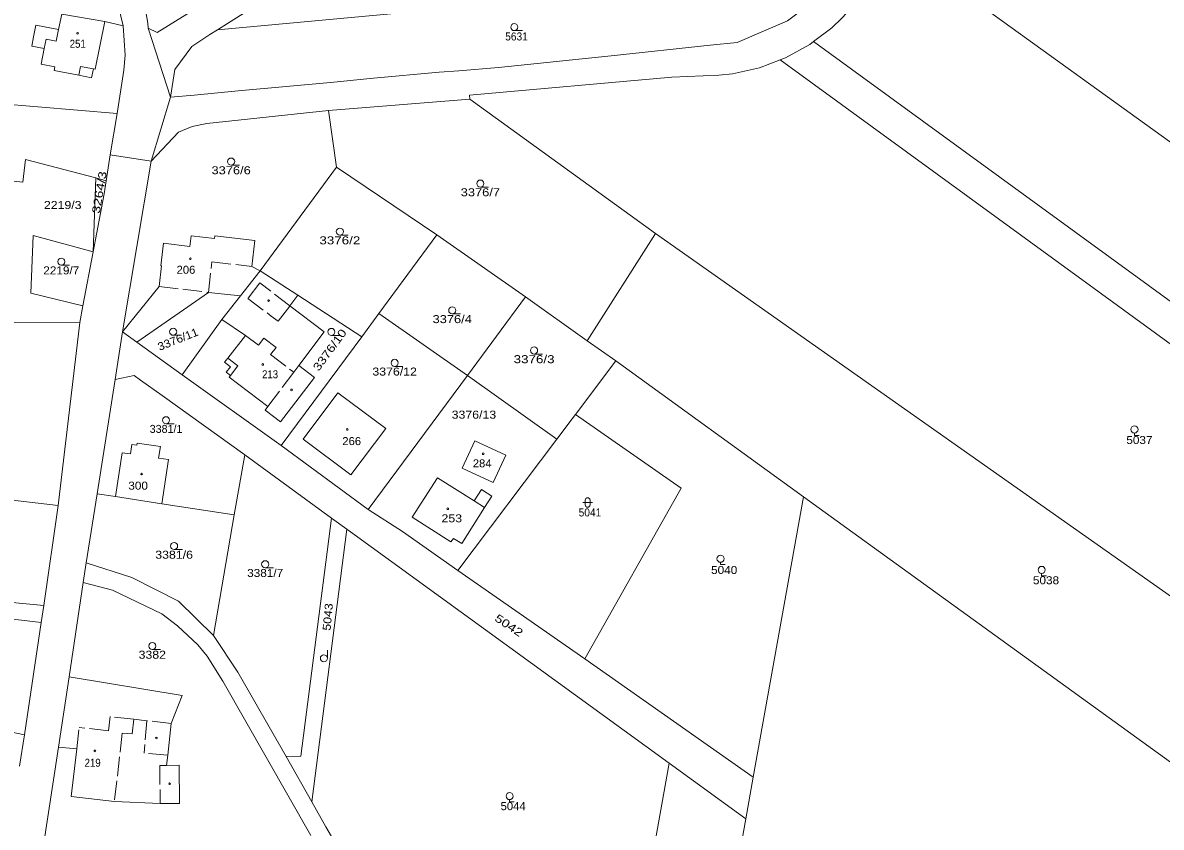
# Model space of a CAD drawing. Extents: x -590528 to -586543, y -1119609 to -1116685.
# Drawn here: x -588604.8 to -588363.1, y -1118023.6 to -1117852.7 of the extents above; entities that cross this region are included whole.
import ezdxf
from ezdxf.enums import TextEntityAlignment as Align

# ---------------------------------------------------------------- set-up
doc = ezdxf.new("R2010")
doc.units = 0
doc.header["$LTSCALE"] = 0.68
doc.linetypes.add('LONG_DASHED', pattern=[7.5, 6, -1.5])
for name, color, linetype, lineweight in [('1', 7, 'Continuous', 13), ('2', 7, 'LONG_DASHED', 13), ('3', 7, 'Continuous', 13), ('6', 7, 'Continuous', 13)]:
    doc.layers.add(name, color=color, linetype=linetype, lineweight=lineweight)

msp = doc.modelspace()

# ---------------------------------------------------------------- linework, layer by layer
at = {"layer": '1'}
for p, q in [((-588417.18, -1117837.61), (-588270.98, -1117943.18)), ((-588585.36, -1117845.73), (-588583.47, -1117853.36)), ((-588587.41, -1117852.47), (-588583.47, -1117853.36)), ((-588436.89, -1117856.73), (-588289.86, -1117963.81)), ((-588443.99, -1117860.6), (-588299, -1117966.2)), ((-588589.8, -1117862.5), (-588589.41, -1117862.58)), ((-588617.56, -1117869.2), (-588584.77, -1117872)), ((-588573.44, -1117868.51), (-588577.57, -1117882.1)), ((-588584.77, -1117872), (-588586.22, -1117880.79)), ((-588538.19, -1117883.42), (-588539.87, -1117871.36)), ((-588568.82, -1117874.77), (-588565.75, -1117874.14)), ((-588577.57, -1117882.1), (-588571.73, -1117875.95)), ((-588571.73, -1117875.95), (-588568.82, -1117874.77)), ((-588586.22, -1117880.79), (-588587.08, -1117886.28)), ((-588586.22, -1117880.79), (-588577.57, -1117882.1)), ((-588577.57, -1117882.1), (-588583.66, -1117918.35)), ((-588589.88, -1117901.39), (-588589.29, -1117885.69)), ((-588587.08, -1117886.28), (-588587.54, -1117889.06)), ((-588602.58, -1117897.93), (-588603.08, -1117910.13)), ((-588589.88, -1117901.39), (-588602.58, -1117897.93)), ((-588569.06, -1117897.94), (-588569.34, -1117900.22)), ((-588564.1, -1117898.55), (-588569.06, -1117897.94)), ((-588564.02, -1117897.96), (-588564.1, -1117898.55)), ((-588555.53, -1117899), (-588564.02, -1117897.96)), ((-588516.85, -1117897.74), (-588498.06, -1117910.93)), ((-588470.44, -1117897.46), (-588324.73, -1118000.18)), ((-588574.9, -1117899.54), (-588575.49, -1117904.32)), ((-588569.34, -1117900.22), (-588574.9, -1117899.54)), ((-588556.2, -1117904.51), (-588555.53, -1117899)), ((-588575.34, -1117904.34), (-588575.87, -1117908.71)), ((-588575.49, -1117904.32), (-588575.34, -1117904.34)), ((-588556.2, -1117904.51), (-588554.41, -1117905.4)), ((-588592.06, -1117912.86), (-588603.08, -1117910.13)), ((-588575.87, -1117908.71), (-588583.66, -1117918.35)), ((-588565.39, -1117909.98), (-588580.55, -1117920.58)), ((-588565.39, -1117909.98), (-588558.59, -1117910.71)), ((-588548.08, -1117912.83), (-588546.37, -1117910.61)), ((-588540.82, -1117918.39), (-588548.08, -1117912.83)), ((-588484.94, -1117920.26), (-588498.06, -1117910.93)), ((-588592.7, -1117916.38), (-588597.27, -1117955.25)), ((-588570.94, -1117927.5), (-588562.55, -1117915.74)), ((-588562.55, -1117915.74), (-588557.52, -1117919.11)), ((-588583.66, -1117918.35), (-588580.55, -1117920.58)), ((-588532.81, -1117919.4), (-588549.96, -1117942.53)), ((-588546.22, -1117925.54), (-588540.82, -1117918.39)), ((-588580.55, -1117920.58), (-588570.94, -1117927.5)), ((-588439.06, -1117953.37), (-588478.89, -1117924.55)), ((-588546.22, -1117925.54), (-588542.88, -1117928.08)), ((-588585.22, -1117928.51), (-588589.01, -1117952.76)), ((-588575.18, -1117931.9), (-588579.81, -1117928.6)), ((-588552.75, -1117934.24), (-588561.01, -1117928.02)), ((-588575.18, -1117931.9), (-588557.68, -1117944.46)), ((-588552.75, -1117934.24), (-588553.34, -1117935.02)), ((-588464.99, -1117951.53), (-588487.42, -1117935.9)), ((-588557.68, -1117944.46), (-588559.9, -1117957.23)), ((-588539.23, -1117957.91), (-588557.68, -1117944.46)), ((-588516.76, -1117949.37), (-588522.13, -1117957.7)), ((-588597.27, -1117955.25), (-588624.74, -1117952.12)), ((-588589.01, -1117952.76), (-588591.33, -1117967.41)), ((-588439.06, -1117953.37), (-588306.86, -1118049.02)), ((-588597.27, -1117955.25), (-588600.36, -1117976.47)), ((-588575.25, -1117954.87), (-588559.9, -1117957.23)), ((-588531.43, -1117956.07), (-588524.16, -1117960.8)), ((-588559.9, -1117957.23), (-588564.34, -1117982.82)), ((-588545.75, -1118008.5), (-588539.23, -1117957.91)), ((-588535.99, -1117960.26), (-588539.23, -1117957.91)), ((-588524.16, -1117960.8), (-588512.39, -1117969.08)), ((-588571.71, -1117975.59), (-588581.67, -1117970.56)), ((-588628.23, -1117973.84), (-588600.36, -1117976.47)), ((-588564.34, -1117982.82), (-588571.71, -1117975.59)), ((-588600.89, -1117980.09), (-588600.36, -1117976.47)), ((-588608.69, -1117979.19), (-588600.89, -1117980.09)), ((-588600.89, -1117980.09), (-588604.44, -1118003.96)), ((-588559.12, -1117990.64), (-588564.34, -1117982.82)), ((-588562.31, -1117992.56), (-588543.64, -1118025.35)), ((-588548.85, -1118008.56), (-588559.12, -1117990.64)), ((-588573.26, -1118001.55), (-588570.99, -1117995.58)), ((-588574.03, -1118008.28), (-588573.26, -1118001.55)), ((-588604.44, -1118003.96), (-588605.52, -1118010.57)), ((-588600.51, -1118028.32), (-588597.22, -1118006.55)), ((-588594.52, -1118017.03), (-588593.36, -1118006.95)), ((-588574.28, -1118010.44), (-588574.03, -1118008.28)), ((-588548.85, -1118008.56), (-588545.75, -1118008.5)), ((-588543.46, -1118018.15), (-588548.85, -1118008.56)), ((-588571.6, -1118010.42), (-588574.28, -1118010.44)), ((-588571.54, -1118018.52), (-588571.6, -1118010.42)), ((-588451.28, -1118021.8), (-588467.56, -1118009.97)), ((-588585.33, -1118018.08), (-588594.52, -1118017.03)), ((-588575.64, -1118018.55), (-588585.33, -1118018.08)), ((-588575.64, -1118018.55), (-588571.54, -1118018.52))]:
    msp.add_line(p, q, dxfattribs=at)
for points in [[(-588436.89, -1117856.73), (-588432.98, -1117853.83), (-588430.89, -1117851.77), (-588424.08, -1117844.39), (-588417.18, -1117837.61), (-588385.65, -1117806.64)], [(-588514.05, -1117825.76), (-588545.49, -1117843.44), (-588552.09, -1117847.24), (-588558.61, -1117851.17), (-588563.45, -1117854.2), (-588515.09, -1117849.79)], [(-588579.44, -1117845.88), (-588578.22, -1117852.82), (-588578.15, -1117853.87), (-588576.25, -1117854.8), (-588570, -1117850.87), (-588560.11, -1117845.04), (-588543.67, -1117835.8), (-588534.47, -1117830.19)], [(-588431.73, -1117842.18), (-588438.44, -1117849.32), (-588442.39, -1117852.33), (-588453.1, -1117856.88), (-588458.84, -1117857.49), (-588479.87, -1117859.78), (-588503.81, -1117862.19), (-588512.2, -1117862.93), (-588516.4, -1117863.24)], [(-588596.48, -1117850.88), (-588597.22, -1117854.15), (-588602.02, -1117853.2), (-588602.52, -1117855.7), (-588602.91, -1117857.66), (-588600.26, -1117858.18), (-588600.92, -1117861.52), (-588597.98, -1117862.1), (-588598.12, -1117862.83)], [(-588596.48, -1117850.88), (-588587.41, -1117852.47), (-588589.41, -1117862.58)], [(-588583.47, -1117853.36), (-588583.09, -1117859.57), (-588583.33, -1117862.78), (-588584.77, -1117872)], [(-588578.15, -1117853.87), (-588573.44, -1117868.51), (-588572.49, -1117862.67), (-588568.92, -1117857.74), (-588565.07, -1117855.21), (-588563.45, -1117854.2)], [(-588436.89, -1117856.73), (-588437.7, -1117857.34), (-588442.86, -1117860.17), (-588443.99, -1117860.6)], [(-588443.99, -1117860.6), (-588448.36, -1117862.26), (-588454.09, -1117863.59), (-588457.02, -1117863.85), (-588467.02, -1117864.25), (-588509.94, -1117868.1), (-588509.86, -1117868.94)], [(-588598.12, -1117862.83), (-588592.89, -1117863.86), (-588590.18, -1117864.4), (-588589.8, -1117862.5)], [(-588516.4, -1117863.24), (-588530.33, -1117864.51), (-588539.45, -1117865.43), (-588559.08, -1117867.21), (-588568.43, -1117868.13), (-588573.44, -1117868.51)], [(-588565.75, -1117874.14), (-588539.87, -1117871.36), (-588509.86, -1117868.94)], [(-588509.86, -1117868.94), (-588470.44, -1117897.46), (-588484.94, -1117920.26)], [(-588628.02, -1117884.13), (-588604.82, -1117886.59), (-588604.22, -1117881.75)], [(-588604.22, -1117881.75), (-588589.29, -1117885.69), (-588587.08, -1117886.28)], [(-588554.41, -1117905.4), (-588538.19, -1117883.42), (-588516.85, -1117897.74)], [(-588587.54, -1117889.06), (-588589.88, -1117901.39), (-588592.06, -1117912.86)], [(-588516.85, -1117897.74), (-588529.18, -1117914.48), (-588532.81, -1117919.4)], [(-588562.55, -1117915.74), (-588558.59, -1117910.71), (-588554.41, -1117905.4)], [(-588532.81, -1117919.4), (-588546.37, -1117910.61), (-588554.41, -1117905.4)], [(-588592.06, -1117912.86), (-588592.7, -1117916.38), (-588608.5, -1117916.3)], [(-588498.06, -1117910.93), (-588510.36, -1117927.65), (-588491.42, -1117941.17)], [(-588531.43, -1117956.07), (-588510.36, -1117927.65), (-588529.18, -1117914.48)], [(-588579.81, -1117928.6), (-588581.12, -1117927.63), (-588585.22, -1117928.51), (-588583.66, -1117918.35)], [(-588561.01, -1117928.02), (-588560.73, -1117927.62), (-588561.62, -1117926.93), (-588560.73, -1117925.79), (-588561.94, -1117924.83), (-588561.24, -1117923.94), (-588557.52, -1117919.11)], [(-588484.94, -1117920.26), (-588478.89, -1117924.55), (-588487.42, -1117935.9), (-588488.15, -1117936.87), (-588491.42, -1117941.17), (-588512.39, -1117969.08)], [(-588570.94, -1117927.5), (-588549.96, -1117942.53), (-588531.43, -1117956.07)], [(-588542.88, -1117928.08), (-588550.07, -1117937.51), (-588553.34, -1117935.02)], [(-588580.53, -1117941.99), (-588580.6, -1117942.43), (-588581.63, -1117942.32), (-588581.92, -1117944.3)], [(-588575.95, -1117945.17), (-588575.58, -1117942.69), (-588580.53, -1117941.99)], [(-588581.92, -1117944.3), (-588583.73, -1117944.08), (-588585.13, -1117953.35)], [(-588575.25, -1117954.87), (-588573.87, -1117945.47), (-588575.95, -1117945.17)], [(-588522.13, -1117957.7), (-588513.88, -1117962.97), (-588513.34, -1117962.24), (-588511.58, -1117963.34), (-588506.75, -1117955.7), (-588505.21, -1117953.24), (-588507.41, -1117951.85), (-588508.93, -1117954.27), (-588516.76, -1117949.37)], [(-588512.39, -1117969.08), (-588485.44, -1117987.82), (-588464.99, -1117951.53)], [(-588589.01, -1117952.76), (-588585.13, -1117953.35), (-588575.25, -1117954.87)], [(-588485.44, -1117987.82), (-588449.7, -1118012.92), (-588439.06, -1117953.37)], [(-588535.99, -1117960.26), (-588543.46, -1118018.15), (-588540.46, -1118023.48), (-588535.88, -1118031.38), (-588522.31, -1118054.62)], [(-588483.2, -1118097.51), (-588467.56, -1118009.97), (-588535.99, -1117960.26)], [(-588581.67, -1117970.56), (-588591.33, -1117967.41), (-588591.97, -1117971.63), (-588585.75, -1117973.23), (-588575.29, -1117978.25)], [(-588570.99, -1117995.58), (-588594.97, -1117991.63), (-588591.97, -1117971.63)], [(-588575.29, -1117978.25), (-588571.97, -1117980.79), (-588567.62, -1117984.85)], [(-588567.62, -1117984.85), (-588565.67, -1117987.22), (-588562.31, -1117992.56)], [(-588604.44, -1118003.96), (-588627.73, -1117999.04), (-588628.69, -1117990.01)], [(-588593.36, -1118006.95), (-588597.22, -1118006.55), (-588594.97, -1117991.63)], [(-588458.27, -1118060.91), (-588451.28, -1118021.8), (-588449.7, -1118012.92)]]:
    msp.add_lwpolyline(points, dxfattribs=at)
for points in [[(-588537.94, -1117931.3), (-588545.29, -1117941.14), (-588535.14, -1117948.74), (-588527.7, -1117938.91)], [(-588511.48, -1117947.3), (-588508.85, -1117941.49), (-588502.26, -1117944.53), (-588504.95, -1117950.33)]]:
    msp.add_lwpolyline(points, close=True, dxfattribs=at)
at = {"layer": '2'}
for p, q in [((-588597.22, -1117854.15), (-588597.71, -1117856.65)), ((-588599.87, -1117856.22), (-588600.26, -1117858.18)), ((-588597.71, -1117856.65), (-588599.87, -1117856.22)), ((-588592.53, -1117861.99), (-588592.89, -1117863.86)), ((-588592.53, -1117861.99), (-588589.8, -1117862.5)), ((-588552.75, -1117934.24), (-588547.27, -1117926.93)), ((-588508.93, -1117954.27), (-588506.75, -1117955.7)), ((-588586.23, -1118000.06), (-588586.58, -1118003.09)), ((-588593.36, -1118006.95), (-588592.84, -1118002.38)), ((-588586.58, -1118003.09), (-588592.84, -1118002.38)), ((-588581.61, -1118003.76), (-588581.25, -1118000.63)), ((-588578.45, -1118000.95), (-588579.05, -1118007.85)), ((-588573.26, -1118001.55), (-588578.45, -1118000.95)), ((-588583.67, -1118003.58), (-588585.33, -1118018.08)), ((-588581.61, -1118003.76), (-588583.67, -1118003.58)), ((-588574.03, -1118008.28), (-588579.05, -1118007.85)), ((-588575.7, -1118010.43), (-588575.64, -1118018.55)), ((-588575.7, -1118010.43), (-588574.28, -1118010.44))]:
    msp.add_line(p, q, dxfattribs=at)
for points in [[(-588575.87, -1117908.71), (-588565.39, -1117909.98), (-588564.64, -1117903.47), (-588556.2, -1117904.51)], [(-588554.48, -1117907.93), (-588556.99, -1117911.25), (-588552.04, -1117915.03), (-588550.61, -1117916.12)], [(-588550.61, -1117916.12), (-588548.08, -1117912.83), (-588554.48, -1117907.93)], [(-588557.52, -1117919.11), (-588554.78, -1117921.2), (-588553.63, -1117919.7), (-588551.03, -1117921.67), (-588552.19, -1117923.18)], [(-588560.73, -1117927.62), (-588559.14, -1117925.61), (-588561.24, -1117923.94)], [(-588552.19, -1117923.18), (-588547.27, -1117926.93), (-588546.22, -1117925.54)], [(-588578.45, -1118000.95), (-588581.25, -1118000.63), (-588586.23, -1118000.06)]]:
    msp.add_lwpolyline(points, dxfattribs=at)
at = {"layer": '6'}
for p, q in [((-588500.44, -1117854.39), (-588498.69, -1117854.39)), ((-588560.56, -1117882.95), (-588558.81, -1117882.95)), ((-588507.64, -1117887.62), (-588505.89, -1117887.62)), ((-588537.48, -1117897.83), (-588535.73, -1117897.83)), ((-588596.63, -1117904.21), (-588594.88, -1117904.21)), ((-588513.62, -1117914.56), (-588511.87, -1117914.56)), ((-588572.87, -1117919.1), (-588571.12, -1117919.1)), ((-588539.27, -1117919.12), (-588537.52, -1117919.12)), ((-588496.23, -1117923.07), (-588494.48, -1117923.07)), ((-588525.84, -1117925.7), (-588524.09, -1117925.7)), ((-588574.38, -1117937.88), (-588572.63, -1117937.88)), ((-588485.36, -1117955.11), (-588485.36, -1117954.11)), ((-588484.36, -1117955.11), (-588484.36, -1117954.11)), ((-588485.86, -1117954.61), (-588483.86, -1117954.61)), ((-588572.67, -1117964.6), (-588570.92, -1117964.6)), ((-588553.33, -1117968.47), (-588551.58, -1117968.47)), ((-588577.3, -1117985.84), (-588575.55, -1117985.84)), ((-588540.12, -1117987.69), (-588540.12, -1117985.94))]:
    msp.add_line(p, q, dxfattribs=at)
for points in [[(-588368.75, -1117939.85), (-588368.75, -1117940.35), (-588367.75, -1117940.35)], [(-588456.65, -1117967.31), (-588456.65, -1117967.81), (-588455.65, -1117967.81)], [(-588388.46, -1117969.67), (-588388.46, -1117970.17), (-588387.46, -1117970.17)], [(-588501.43, -1118017.71), (-588501.43, -1118018.21), (-588500.43, -1118018.21)]]:
    msp.add_lwpolyline(points, dxfattribs=at)
for centre, radius in [((-588593.1802, -1117854.9504), 0.175), ((-588500.44, -1117853.64), 0.75), ((-588560.56, -1117882.2), 0.75), ((-588507.64, -1117886.87), 0.75), ((-588537.48, -1117897.08), 0.75), ((-588596.63, -1117903.46), 0.75), ((-588569.2102, -1117902.8504), 0.175), ((-588552.6002, -1117911.7404), 0.175), ((-588513.62, -1117913.81), 0.75), ((-588572.87, -1117918.35), 0.75), ((-588539.27, -1117918.37), 0.75), ((-588496.23, -1117922.32), 0.75), ((-588553.8402, -1117925.2904), 0.175), ((-588525.84, -1117924.95), 0.75), ((-588547.7302, -1117930.6904), 0.175), ((-588574.38, -1117937.13), 0.75), ((-588535.8902, -1117939.1004), 0.175), ((-588368.75, -1117939.1), 0.75), ((-588507.0402, -1117944.2604), 0.175), ((-588579.5602, -1117948.5704), 0.175), ((-588514.5602, -1117955.9404), 0.175), ((-588572.67, -1117963.85), 0.75), ((-588456.65, -1117966.56), 0.75), ((-588553.33, -1117967.72), 0.75), ((-588388.46, -1117968.92), 0.75), ((-588577.3, -1117985.09), 0.75), ((-588540.87, -1117987.69), 0.75), ((-588576.4202, -1118004.6104), 0.175), ((-588589.4902, -1118007.3604), 0.175), ((-588573.6302, -1118014.3304), 0.175), ((-588501.43, -1118016.96), 0.75)]:
    msp.add_circle(centre, radius, dxfattribs=at)
for centre, start, end in [((-588484.86, -1117954.11), 0, 179.99999), ((-588484.86, -1117955.11), 179.99999, 359.99999)]:
    msp.add_arc(centre, 0.5, start, end, dxfattribs=at)

# ---------------------------------------------------------------- texts
at = {"layer": '3'}
for s, width, p in [('5631', 0.95, (-588502.363, -1117856.48)), ('5037', 1.1, (-588370.483, -1117942.19)), ('5041', 0.95, (-588486.773, -1117957.57)), ('5040', 1.1, (-588458.653, -1117969.79)), ('5038', 1.1, (-588390.313, -1117971.97)), ('5044', 1.05, (-588503.343, -1118019.95))]:
    msp.add_text(s, height=1.7, dxfattribs=dict(at, width=width)).set_placement(p)
for s, width, p in [('251', 0.9, (-588593.1305, -1117858.03)), ('3376/6', 1.2, (-588560.56, -1117884.9)), ('3376/7', 1.2, (-588507.64, -1117889.57)), ('2219/3', 1.15, (-588596.3205, -1117892.28)), ('3376/2', 1.25, (-588537.4805, -1117899.78)), ('2219/7', 1.1, (-588596.6305, -1117906.16)), ('206', 1.05, (-588570.1505, -1117906.03)), ('3376/4', 1.2, (-588513.62, -1117916.51)), ('3376/3', 1.25, (-588496.23, -1117925.02)), ('213', 0.9, (-588552.2905, -1117928.23)), ('3376/12', 1.15, (-588525.84, -1117927.65)), ('3376/13', 1.15, (-588509.0105, -1117936.8)), ('266', 1.05, (-588534.9605, -1117942.42)), ('284', 1.05, (-588507.2505, -1117947.14)), ('300', 1.1, (-588580.3105, -1117951.88)), ('253', 1.15, (-588513.7105, -1117958.82)), ('3381/6', 1.15, (-588572.67, -1117966.55)), ('3381/7', 1.1, (-588553.33, -1117970.42)), ('3382', 1.15, (-588577.3005, -1117987.79)), ('219', 0.9, (-588589.9705, -1118010.73))]:
    msp.add_text(s, height=1.7, dxfattribs=dict(at, width=width)).set_placement(p, align=Align.CENTER)
for s, rotation, width, p in [('3264/3', 80.329, 1.3, (-588587.7155, -1117888.8883)), ('3376/11', 21.83, 1.1, (-588571.5541, -1117920.7332)), ('3376/10', 53.915, 1.25, (-588538.9358, -1117922.6996))]:
    msp.add_text(s, height=1.7, rotation=rotation, dxfattribs=dict(at, width=width)).set_placement(p, align=Align.CENTER)
msp.add_text('3381/1', height=1.7, dxfattribs=at).set_placement((-588574.38, -1117939.83), align=Align.CENTER)
for s, rotation, width, p in [('5043', 84.912, 1.15, (-588539.459, -1117981.884)), ('5042', 326.414, 1.3, (-588504.782, -1117979.601))]:
    msp.add_text(s, height=1.7, rotation=rotation, dxfattribs=dict(at, width=width)).set_placement(p)

doc.saveas('drawing.dxf')
